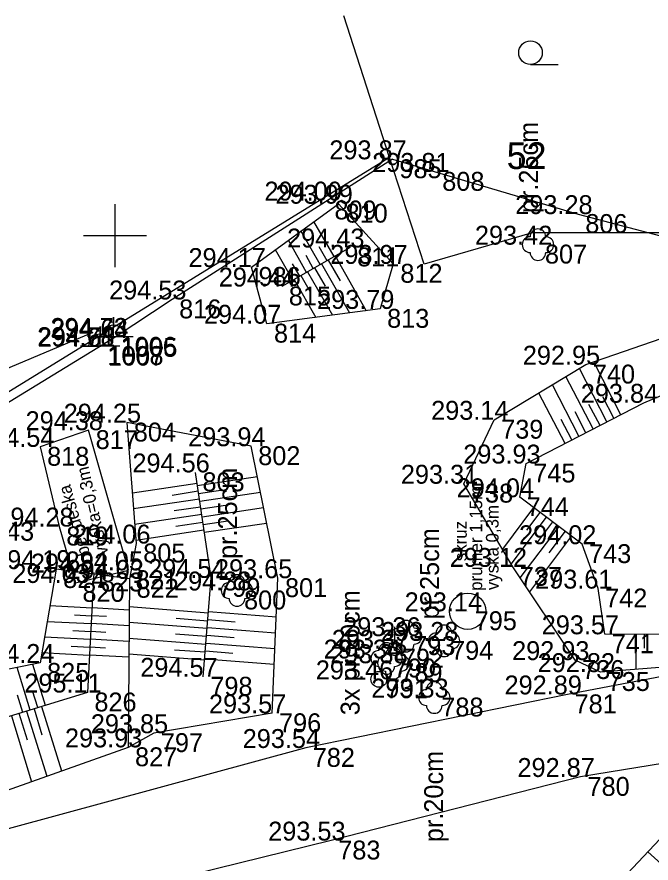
# Model space of a CAD drawing. Extents: x -599970 to -599524, y -1154772 to -1154457.
# Drawn here: x -599753.11 to -599732.99, y -1154619.91 to -1154593.05 of the extents above; entities that cross this region are included whole.
import ezdxf

# ---------------------------------------------------------------- set-up
doc = ezdxf.new("R2010")
doc.units = 0
for name, color, linetype in [('Z-KANALIZACNI SACHTY VPUSTI', 7, 'Continuous'), ('Z-KATASTRALNI MAPA', 7, 'Continuous'), ('Z-KRIZKY CTVERCOVE SITE', 7, 'Continuous'), ('Z-OCHRANNA TYC VODOVODU', 7, 'Continuous'), ('Z-PLOT DRATENY', 7, 'Continuous'), ('Z-PODROBNE BODY', 7, 'Continuous'), ('Z-PODROBNE BODY-CISLO', 7, 'Continuous'), ('Z-PODROBNE BODY-VYSKA', 7, 'Continuous'), ('Z-POPISY OBJEKTU A ZPEVNENYCH PLOCH', 7, 'Continuous'), ('Z-PRUMERY KMENU STROMU', 7, 'Continuous'), ('Z-SCHODY', 7, 'Continuous'), ('Z-SRAFOVANI SVAHU', 7, 'Continuous'), ('Z-STROMY ZNACKY KULTUR', 7, 'Continuous'), ('Z-TERENNI HRANY PATY', 7, 'Continuous'), ('Z-VYSKOVE BODY', 7, 'Continuous'), ('Z-ZPEVNENE PLOCHY', 7, 'Continuous')]:
    doc.layers.add(name, color=color, linetype=linetype)

msp = doc.modelspace()

# ---------------------------------------------------------------- linework, layer by layer
at = {"layer": 'Z-KANALIZACNI SACHTY VPUSTI'}
msp.add_circle((-599741.63, -1154614.08), 0.25, dxfattribs=at)
at = {"layer": 'Z-KATASTRALNI MAPA'}
for p, q in [((-599741.29, -1154597.51), (-599742.74, -1154593.02)), ((-599736.816, -1154594.56), (-599735.941, -1154594.56)), ((-599741.29, -1154597.51), (-599768.28, -1154614.14))]:
    msp.add_line(p, q, dxfattribs=at)
msp.add_lwpolyline([(-599730.43, -1154599.91), (-599736.76, -1154599.9), (-599740.19, -1154600.9), (-599741.29, -1154597.51)], dxfattribs=at)
msp.add_circle((-599736.816, -1154594.185), 0.375, dxfattribs=at)
at = {"layer": 'Z-KRIZKY CTVERCOVE SITE'}
for p, q in [((-599750, -1154601), (-599750, -1154599)), ((-599749, -1154600), (-599751, -1154600))]:
    msp.add_line(p, q, dxfattribs=at)
at = {"layer": 'Z-OCHRANNA TYC VODOVODU'}
msp.add_line((-599741.12, -1154612.885), (-599741.12, -1154612.414), dxfattribs=at)
msp.add_circle((-599741.12, -1154613.11), 0.225, dxfattribs=at)
at = {"layer": 'Z-PLOT DRATENY'}
for points in [[(-599741.2, -1154597.57), (-599748.19, -1154602.02), (-599750.03, -1154603.24), (-599757.54, -1154607.83), (-599759.8, -1154609.21), (-599765.35, -1154612.62), (-599767.84, -1154614.15), (-599771.68, -1154615.78), (-599777.02, -1154618.08), (-599780.14, -1154619.26), (-599783.61, -1154619.05), (-599791.83, -1154621.49)], [(-599741.2, -1154597.57), (-599735.3, -1154599.31), (-599728.67, -1154601.06), (-599725.81, -1154601.09), (-599719.24, -1154600.72), (-599713.57, -1154600.28), (-599704.41, -1154598.89), (-599697.5, -1154597.88)]]:
    msp.add_lwpolyline(points, dxfattribs=at)
at = {"layer": 'Z-PODROBNE BODY'}
for p, q in [((-599741.2, -1154597.57), (-599741.2, -1154597.57)), ((-599739.84, -1154597.97), (-599739.84, -1154597.97)), ((-599743.26, -1154598.88), (-599743.26, -1154598.88)), ((-599742.91, -1154598.98), (-599742.91, -1154598.98)), ((-599735.3, -1154599.31), (-599735.3, -1154599.31)), ((-599736.58, -1154600.28), (-599736.58, -1154600.28)), ((-599742.54, -1154600.37), (-599742.54, -1154600.37)), ((-599745.67, -1154600.99), (-599745.67, -1154600.99)), ((-599741.17, -1154600.89), (-599741.17, -1154600.89)), ((-599744.71, -1154601.61), (-599744.71, -1154601.61)), ((-599748.19, -1154602.02), (-599748.19, -1154602.02)), ((-599741.59, -1154602.32), (-599741.59, -1154602.32)), ((-599745.18, -1154602.79), (-599745.18, -1154602.79)), ((-599750.05, -1154603.21), (-599750.05, -1154603.21)), ((-599750.03, -1154603.24), (-599750.03, -1154603.24)), ((-599750.47, -1154603.5), (-599750.47, -1154603.5)), ((-599750.45, -1154603.52), (-599750.45, -1154603.52)), ((-599735.06, -1154604.09), (-599735.06, -1154604.09)), ((-599733.22, -1154605.3), (-599733.22, -1154605.3)), ((-599749.63, -1154605.93), (-599749.63, -1154605.93)), ((-599737.97, -1154605.84), (-599737.97, -1154605.84)), ((-599750.84, -1154606.17), (-599750.84, -1154606.17)), ((-599752.38, -1154606.7), (-599752.38, -1154606.7)), ((-599745.68, -1154606.68), (-599745.68, -1154606.68)), ((-599736.95, -1154607.23), (-599736.95, -1154607.23)), ((-599747.45, -1154607.51), (-599747.45, -1154607.51)), ((-599738.93, -1154607.87), (-599738.93, -1154607.87)), ((-599737.16, -1154608.3), (-599737.16, -1154608.3)), ((-599751.77, -1154609.23), (-599751.77, -1154609.23)), ((-599749.33, -1154609.77), (-599749.33, -1154609.77)), ((-599735.18, -1154609.79), (-599735.18, -1154609.79)), ((-599737.38, -1154610.51), (-599737.38, -1154610.51)), ((-599751.87, -1154610.58), (-599751.87, -1154610.58)), ((-599750.67, -1154610.69), (-599750.67, -1154610.69)), ((-599749.57, -1154610.62), (-599749.57, -1154610.62)), ((-599751.26, -1154611.02), (-599751.26, -1154611.02)), ((-599749.54, -1154610.89), (-599749.54, -1154610.89)), ((-599746.95, -1154610.86), (-599746.95, -1154610.86)), ((-599744.83, -1154610.87), (-599744.83, -1154610.87)), ((-599746.13, -1154611.26), (-599746.13, -1154611.26)), ((-599734.67, -1154611.2), (-599734.67, -1154611.2)), ((-599738.81, -1154611.92), (-599738.81, -1154611.92)), ((-599734.46, -1154612.65), (-599734.46, -1154612.65)), ((-599740.76, -1154612.71), (-599740.76, -1154612.71)), ((-599739.56, -1154612.86), (-599739.56, -1154612.86)), ((-599741.12, -1154613.11), (-599741.12, -1154613.11)), ((-599741.38, -1154613.42), (-599741.38, -1154613.42)), ((-599752.38, -1154613.56), (-599752.38, -1154613.56)), ((-599741.17, -1154613.57), (-599741.17, -1154613.57)), ((-599735.4, -1154613.47), (-599735.4, -1154613.47)), ((-599747.2, -1154614), (-599747.2, -1154614)), ((-599734.59, -1154613.85), (-599734.59, -1154613.85)), ((-599741.63, -1154614.08), (-599741.63, -1154614.08)), ((-599750.88, -1154614.5), (-599750.88, -1154614.5)), ((-599739.87, -1154614.66), (-599739.87, -1154614.66)), ((-599735.64, -1154614.56), (-599735.64, -1154614.56)), ((-599745.02, -1154615.16), (-599745.02, -1154615.16)), ((-599748.77, -1154615.79), (-599748.77, -1154615.79)), ((-599749.59, -1154616.24), (-599749.59, -1154616.24)), ((-599743.95, -1154616.26), (-599743.95, -1154616.26)), ((-599735.23, -1154617.18), (-599735.23, -1154617.18)), ((-599743.14, -1154619.2), (-599743.14, -1154619.2))]:
    msp.add_line(p, q, dxfattribs=at)
at = {"layer": 'Z-SCHODY'}
msp.add_circle((-599738.81, -1154611.92), 0.575, dxfattribs=at)
at = {"layer": 'Z-SRAFOVANI SVAHU'}
for points in [[(-599743.05, -1154600.66), (-599743.69, -1154599.55)], [(-599743.49, -1154600.91), (-599744.1, -1154599.84)], [(-599743.92, -1154601.16), (-599744.5, -1154600.14)], [(-599744.36, -1154601.41), (-599744.91, -1154600.44)], [(-599743.27, -1154600.79), (-599743.52, -1154600.35)], [(-599743.71, -1154601.04), (-599743.94, -1154600.62)], [(-599743.24, -1154600.77), (-599742.86, -1154601.43)], [(-599743.02, -1154600.64), (-599742.03, -1154602.38)], [(-599744.14, -1154601.28), (-599744.37, -1154600.89)], [(-599743.67, -1154601.02), (-599743.33, -1154601.6)], [(-599743.45, -1154600.89), (-599742.56, -1154602.45)], [(-599744.1, -1154601.26), (-599743.81, -1154601.78)], [(-599743.89, -1154601.14), (-599743.1, -1154602.52)], [(-599744.32, -1154601.39), (-599743.63, -1154602.59)], [(-599733.95, -1154605.68), (-599734.81, -1154604)], [(-599734.39, -1154605.91), (-599735.26, -1154604.21)], [(-599734.83, -1154606.13), (-599735.69, -1154604.47)], [(-599735.28, -1154606.36), (-599736.12, -1154604.73)], [(-599735.72, -1154606.59), (-599736.55, -1154604.99)], [(-599734.17, -1154605.79), (-599734.52, -1154605.11)], [(-599734.61, -1154606.02), (-599734.96, -1154605.35)], [(-599735.06, -1154606.25), (-599735.4, -1154605.59)], [(-599735.5, -1154606.48), (-599735.84, -1154605.83)], [(-599747.39, -1154607.93), (-599745.48, -1154607.64)], [(-599747.4, -1154607.86), (-599749.45, -1154608.17)], [(-599747.35, -1154608.18), (-599746.58, -1154608.06)], [(-599747.32, -1154608.36), (-599749.42, -1154608.67)], [(-599747.36, -1154608.11), (-599748.19, -1154608.24)], [(-599747.31, -1154608.42), (-599745.38, -1154608.14)], [(-599747.29, -1154608.61), (-599748.13, -1154608.73)], [(-599747.28, -1154608.67), (-599746.5, -1154608.55)], [(-599747.24, -1154608.92), (-599745.29, -1154608.63)], [(-599736.72, -1154608.63), (-599737.71, -1154609.95)], [(-599747.25, -1154608.85), (-599749.38, -1154609.17)], [(-599736.52, -1154608.78), (-599736.94, -1154609.34)], [(-599747.21, -1154609.1), (-599748.07, -1154609.23)], [(-599747.2, -1154609.16), (-599746.42, -1154609.05)], [(-599747.17, -1154609.41), (-599745.19, -1154609.12)], [(-599736.32, -1154608.93), (-599737.44, -1154610.42)], [(-599736.12, -1154609.08), (-599736.59, -1154609.71)], [(-599747.18, -1154609.35), (-599749.34, -1154609.67)], [(-599735.92, -1154609.23), (-599737.15, -1154610.86)], [(-599735.72, -1154609.38), (-599736.23, -1154610.06)], [(-599735.52, -1154609.53), (-599736.85, -1154611.3)], [(-599750.73, -1154611.82), (-599752.07, -1154611.75)], [(-599750.73, -1154611.8), (-599749.55, -1154611.87)], [(-599747.04, -1154611.98), (-599749.55, -1154611.78)], [(-599750.75, -1154612.07), (-599751.29, -1154612.04)], [(-599750.75, -1154612.05), (-599750.27, -1154612.08)], [(-599747.04, -1154611.93), (-599744.88, -1154612.1)], [(-599750.76, -1154612.32), (-599752.16, -1154612.25)], [(-599750.76, -1154612.3), (-599749.55, -1154612.37)], [(-599747.08, -1154612.47), (-599749.55, -1154612.28)], [(-599747.06, -1154612.23), (-599748.06, -1154612.15)], [(-599747.06, -1154612.18), (-599746.19, -1154612.25)], [(-599750.77, -1154612.57), (-599751.34, -1154612.54)], [(-599750.77, -1154612.55), (-599750.29, -1154612.58)], [(-599747.1, -1154612.72), (-599748.08, -1154612.65)], [(-599747.07, -1154612.43), (-599744.91, -1154612.6)], [(-599750.79, -1154612.82), (-599752.24, -1154612.74)], [(-599750.79, -1154612.8), (-599749.56, -1154612.87)], [(-599747.12, -1154612.97), (-599749.56, -1154612.78)], [(-599747.09, -1154612.68), (-599746.22, -1154612.75)], [(-599733.46, -1154612.66), (-599733.47, -1154613.76)], [(-599733.21, -1154612.66), (-599733.21, -1154613.09)], [(-599750.8, -1154613.07), (-599751.39, -1154613.04)], [(-599750.8, -1154613.05), (-599750.3, -1154613.08)], [(-599747.14, -1154613.22), (-599748.11, -1154613.15)], [(-599747.13, -1154613.18), (-599746.26, -1154613.25)], [(-599747.11, -1154612.93), (-599744.93, -1154613.1)], [(-599750.82, -1154613.32), (-599752.32, -1154613.24)], [(-599750.81, -1154613.3), (-599749.56, -1154613.37)], [(-599747.16, -1154613.47), (-599749.56, -1154613.28)], [(-599747.15, -1154613.43), (-599744.95, -1154613.6)], [(-599752.69, -1154615.06), (-599753.11, -1154613.71)], [(-599752.21, -1154614.91), (-599752.61, -1154613.61)], [(-599752.45, -1154614.98), (-599752.62, -1154614.45)], [(-599752.93, -1154615.13), (-599753.1, -1154614.58)], [(-599752.57, -1154615.02), (-599752.32, -1154615.84)], [(-599752.33, -1154614.94), (-599751.7, -1154616.99)], [(-599753.29, -1154615.24), (-599752.65, -1154617.33)], [(-599753.05, -1154615.16), (-599752.79, -1154616)], [(-599752.81, -1154615.09), (-599752.17, -1154617.16)], [(-599731.61, -1154620.89), (-599733.09, -1154619.56)]]:
    msp.add_lwpolyline(points, dxfattribs=at)
at = {"layer": 'Z-STROMY ZNACKY KULTUR'}
for centre in [(-599736.58, -1154600.28), (-599746.13, -1154611.26), (-599740.76, -1154612.71), (-599739.56, -1154612.86), (-599741.38, -1154613.42), (-599741.17, -1154613.57), (-599739.87, -1154614.66)]:
    msp.add_circle(centre, 0.00025, dxfattribs=at)
for centre, start, end in [((-599736.83, -1154600.28), 90, 270), ((-599736.58, -1154600.03), 0, 180), ((-599736.33, -1154600.28), 270, 90), ((-599736.58, -1154600.53), 180, 360), ((-599746.13, -1154611.01), 0, 180), ((-599746.38, -1154611.26), 90, 270), ((-599745.88, -1154611.26), 270, 90), ((-599746.13, -1154611.51), 180, 360), ((-599740.76, -1154612.46), 0, 180), ((-599739.56, -1154612.61), 0, 180), ((-599741.01, -1154612.71), 90, 270), ((-599740.51, -1154612.71), 270, 90), ((-599739.81, -1154612.86), 90, 270), ((-599739.31, -1154612.86), 270, 90), ((-599741.38, -1154613.17), 0, 180), ((-599741.63, -1154613.42), 90, 270), ((-599741.17, -1154613.32), 0, 180), ((-599741.13, -1154613.42), 270, 90), ((-599740.76, -1154612.96), 180, 360), ((-599739.56, -1154613.11), 180, 360), ((-599741.42, -1154613.57), 90, 270), ((-599740.92, -1154613.57), 270, 90), ((-599741.38, -1154613.67), 180, 360), ((-599741.17, -1154613.82), 180, 360), ((-599739.87, -1154614.41), 0, 180), ((-599740.12, -1154614.66), 90, 270), ((-599739.62, -1154614.66), 270, 90), ((-599739.87, -1154614.91), 180, 360)]:
    msp.add_arc(centre, 0.25, start, end, dxfattribs=at)
at = {"layer": 'Z-TERENNI HRANY PATY'}
for points in [[(-599745.18, -1154602.79), (-599745.67, -1154600.99), (-599742.91, -1154598.98), (-599741.17, -1154600.89), (-599741.59, -1154602.32)], [(-599729.05, -1154602.01), (-599721.76, -1154601.98), (-599713.7, -1154601.68), (-599707.23, -1154600.75), (-599702.22, -1154599.95), (-599702.11, -1154604.78), (-599703.83, -1154606.55), (-599707.44, -1154607.94), (-599715.66, -1154610.06), (-599723.72, -1154611.89), (-599730.02, -1154613.49), (-599734.59, -1154613.85), (-599735.4, -1154613.47), (-599737.38, -1154610.51), (-599738.93, -1154607.87), (-599737.97, -1154605.84), (-599735.06, -1154604.09), (-599729.05, -1154602.01)], [(-599742.54, -1154600.37), (-599744.71, -1154601.61)], [(-599706.69, -1154601.61), (-599704.55, -1154601.39), (-599703.42, -1154603.18), (-599703.99, -1154604.61), (-599707.71, -1154606.89), (-599711.67, -1154607.23), (-599718.57, -1154608.46), (-599724.85, -1154610.8), (-599730.76, -1154612.67), (-599734.46, -1154612.65)], [(-599741.59, -1154602.32), (-599745.18, -1154602.79)], [(-599734.46, -1154612.65), (-599734.67, -1154611.2), (-599735.18, -1154609.79), (-599737.16, -1154608.3), (-599736.95, -1154607.23), (-599733.22, -1154605.3), (-599730.19, -1154604.02), (-599725.57, -1154603.88), (-599719.1, -1154602.65), (-599713.56, -1154602.84), (-599710.91, -1154602.51)], [(-599749.63, -1154605.93), (-599749.33, -1154609.77), (-599749.54, -1154610.89)], [(-599745.02, -1154615.16), (-599744.83, -1154610.87), (-599745.68, -1154606.68), (-599749.63, -1154605.93)], [(-599747.2, -1154614), (-599746.95, -1154610.86), (-599747.45, -1154607.51)], [(-599749.54, -1154610.89), (-599751.87, -1154610.58), (-599752.38, -1154613.56), (-599757.6, -1154614.61), (-599759.09, -1154612.31), (-599761.33, -1154613.69)], [(-599750.67, -1154610.69), (-599750.88, -1154614.5), (-599755.48, -1154615.91), (-599758.65, -1154615.71), (-599760.14, -1154613.54)], [(-599749.54, -1154610.89), (-599749.59, -1154616.24), (-599757.01, -1154618.88), (-599758.7, -1154617.18), (-599760.39, -1154616), (-599761.33, -1154613.69)], [(-599706.85, -1154650.78), (-599713.18, -1154651.03), (-599721.07, -1154652.91), (-599723.76, -1154645.8), (-599725.1, -1154640.23), (-599727.83, -1154634.18), (-599728.54, -1154633), (-599732.31, -1154631.05), (-599735.11, -1154628.08), (-599735.76, -1154623.86), (-599735.73, -1154623.89), (-599734.76, -1154621.33), (-599730.32, -1154616.62), (-599722.93, -1154615.52), (-599713.66, -1154613.52), (-599712.4, -1154614.76), (-599710.05, -1154618.59), (-599710.54, -1154622.05), (-599712.9, -1154623.66), (-599717.25, -1154628.18), (-599716.96, -1154629.04), (-599714.58, -1154631.6), (-599714.4, -1154633.54), (-599711.28, -1154633.06)], [(-599745.02, -1154615.16), (-599748.77, -1154615.79), (-599749.59, -1154616.24)]]:
    msp.add_lwpolyline(points, dxfattribs=at)
at = {"layer": 'Z-VYSKOVE BODY'}
for p, q in [((-599750.05, -1154602.585), (-599750.05, -1154602.835)), ((-599750.05, -1154602.835), (-599750.05, -1154602.585)), ((-599750.05, -1154603.21), (-599750.05, -1154602.585)), ((-599750.05, -1154602.585), (-599750.05, -1154602.835)), ((-599750.47, -1154602.875), (-599750.47, -1154603.125)), ((-599750.47, -1154603.125), (-599750.47, -1154602.875)), ((-599750.47, -1154603.5), (-599750.47, -1154602.875)), ((-599750.47, -1154602.875), (-599750.47, -1154603.125)), ((-599764.3, -1154608.79), (-599750.7, -1154603.06)), ((-599749.425, -1154603.21), (-599750.675, -1154603.21)), ((-599750.675, -1154603.21), (-599750.05, -1154603.21)), ((-599749.425, -1154603.21), (-599750.05, -1154603.21)), ((-599749.845, -1154603.5), (-599751.095, -1154603.5)), ((-599751.095, -1154603.5), (-599750.47, -1154603.5)), ((-599749.845, -1154603.5), (-599750.47, -1154603.5))]:
    msp.add_line(p, q, dxfattribs=at)
for centre, start, end in [((-599750.05, -1154603.21), 90, 180), ((-599750.05, -1154603.21), 0, 90), ((-599750.47, -1154603.5), 90, 180), ((-599750.47, -1154603.5), 0, 90)]:
    msp.add_arc(centre, 0.375, start, end, dxfattribs=at)
at = {"layer": 'Z-ZPEVNENE PLOCHY'}
for points in [[(-599750.84, -1154606.17), (-599752.38, -1154606.7), (-599751.77, -1154609.23), (-599751.26, -1154611.02), (-599749.57, -1154610.62), (-599750.84, -1154606.17)], [(-599671.02, -1154617.03), (-599671.63, -1154613.35), (-599675.05, -1154613.45), (-599680.32, -1154612.41), (-599686.62, -1154610.91), (-599694.45, -1154609.33), (-599700.34, -1154608.57), (-599705.79, -1154608.71), (-599715.78, -1154610.69), (-599725.58, -1154612.61), (-599730.02, -1154613.49), (-599735.64, -1154614.56), (-599743.95, -1154616.26), (-599754.96, -1154619.25), (-599762.63, -1154622.27), (-599761.65, -1154625.43)], [(-599671.02, -1154617.03), (-599674, -1154617.11), (-599674.74, -1154618.09), (-599672.97, -1154619.61), (-599672.99, -1154619.63), (-599673.43, -1154624.97), (-599672.1, -1154632.73), (-599679.37, -1154632.4), (-599679.21, -1154625.35), (-599679.14, -1154619.7), (-599679.61, -1154616.32), (-599687.06, -1154613.66), (-599695, -1154612.23), (-599700.47, -1154611.47), (-599705.51, -1154611.86), (-599715.16, -1154613.61), (-599724.96, -1154615.5), (-599735.23, -1154617.18), (-599743.14, -1154619.2), (-599754.14, -1154621.91)]]:
    msp.add_lwpolyline(points, dxfattribs=at)

# ---------------------------------------------------------------- texts
at = {"layer": 'Z-KATASTRALNI MAPA'}
msp.add_text('52', height=0.85, dxfattribs=at).set_placement((-599737.573, -1154597.88))
at = {"layer": 'Z-PODROBNE BODY-CISLO'}
for s, p in [(' 985', (-599741.2, -1154598.17)), (' 808', (-599739.84, -1154598.57)), (' 809', (-599743.26, -1154599.48)), (' 810', (-599742.91, -1154599.58)), (' 806', (-599735.3, -1154599.91)), (' 807', (-599736.58, -1154600.88)), (' 811', (-599742.54, -1154600.97)), (' 986', (-599745.67, -1154601.59)), (' 812', (-599741.17, -1154601.49)), (' 815', (-599744.71, -1154602.21)), (' 816', (-599748.19, -1154602.62)), (' 813', (-599741.59, -1154602.92)), (' 814', (-599745.18, -1154603.39)), (' 1006', (-599750.05, -1154603.81)), (' 1005', (-599750.03, -1154603.84)), (' 1008', (-599750.47, -1154604.1)), (' 1007', (-599750.45, -1154604.12)), (' 740', (-599735.06, -1154604.69)), (' 804', (-599749.63, -1154606.53)), (' 739', (-599737.97, -1154606.44)), (' 817', (-599750.84, -1154606.77)), (' 818', (-599752.38, -1154607.3)), (' 802', (-599745.68, -1154607.28)), (' 745', (-599736.95, -1154607.83)), (' 803', (-599747.45, -1154608.11)), (' 738', (-599738.93, -1154608.47)), (' 744', (-599737.16, -1154608.9)), (' 843', (-599754.13, -1154609.68)), (' 819', (-599751.77, -1154609.83)), (' 805', (-599749.33, -1154610.37)), (' 743', (-599735.18, -1154610.39)), (' 737', (-599737.38, -1154611.11)), (' 824', (-599751.87, -1154611.18)), (' 823', (-599750.67, -1154611.29)), (' 821', (-599749.57, -1154611.22)), (' 820', (-599751.26, -1154611.62)), (' 822', (-599749.54, -1154611.49)), (' 799', (-599746.95, -1154611.46)), (' 801', (-599744.83, -1154611.47)), (' 800', (-599746.13, -1154611.86)), (' 742', (-599734.67, -1154611.8)), (' 795', (-599738.81, -1154612.52)), (' 741', (-599734.46, -1154613.25)), (' 793', (-599740.76, -1154613.31)), (' 794', (-599739.56, -1154613.46)), (' 792', (-599741.12, -1154613.71)), (' 790', (-599741.38, -1154614.02)), (' 736', (-599735.4, -1154614.07)), (' 825', (-599752.38, -1154614.16)), (' 789', (-599741.17, -1154614.17)), (' 798', (-599747.2, -1154614.6)), (' 735', (-599734.59, -1154614.45)), (' 791', (-599741.63, -1154614.68)), (' 826', (-599750.88, -1154615.1)), (' 788', (-599739.87, -1154615.26)), (' 781', (-599735.64, -1154615.16)), (' 796', (-599745.02, -1154615.76)), (' 797', (-599748.77, -1154616.39)), (' 827', (-599749.59, -1154616.84)), (' 782', (-599743.95, -1154616.86)), (' 780', (-599735.23, -1154617.78)), (' 783', (-599743.14, -1154619.8))]:
    msp.add_text(s, height=0.6, dxfattribs=at).set_placement(p)
at = {"layer": 'Z-PODROBNE BODY-VYSKA'}
for s, p in [('293.87 ', (-599743.2, -1154597.57)), ('293.81 ', (-599741.84, -1154597.97)), ('294.00 ', (-599745.26, -1154598.88)), ('293.99 ', (-599744.91, -1154598.98)), ('293.28 ', (-599737.3, -1154599.31)), ('294.43 ', (-599744.54, -1154600.37)), ('293.42 ', (-599738.58, -1154600.28)), ('293.97 ', (-599743.17, -1154600.89)), ('294.17 ', (-599747.67, -1154600.99)), ('294.44 ', (-599746.71, -1154601.61)), ('294.53 ', (-599750.19, -1154602.02)), ('293.79 ', (-599743.59, -1154602.32)), ('294.07 ', (-599747.18, -1154602.79)), ('294.73 ', (-599752.05, -1154603.21)), ('294.64 ', (-599752.03, -1154603.24)), ('294.78 ', (-599752.47, -1154603.5)), ('294.61 ', (-599752.45, -1154603.52)), ('292.95 ', (-599737.06, -1154604.09)), ('293.84 ', (-599735.22, -1154605.3)), ('294.25 ', (-599751.63, -1154605.93)), ('293.14 ', (-599739.97, -1154605.84)), ('294.38 ', (-599752.84, -1154606.17)), ('294.54 ', (-599754.38, -1154606.7)), ('293.94 ', (-599747.68, -1154606.68)), ('293.93 ', (-599738.95, -1154607.23)), ('294.56 ', (-599749.45, -1154607.51)), ('293.31 ', (-599740.93, -1154607.87)), ('294.04 ', (-599739.16, -1154608.3)), ('294.28 ', (-599753.77, -1154609.23)), ('294.06 ', (-599751.33, -1154609.77)), ('294.02 ', (-599737.18, -1154609.79)), ('294.19 ', (-599753.87, -1154610.58)), ('293.12 ', (-599739.38, -1154610.51)), ('294.82 ', (-599752.67, -1154610.69)), ('294.05 ', (-599751.57, -1154610.62)), ('294.03 ', (-599753.26, -1154611.02)), ('294.03 ', (-599751.54, -1154610.89)), ('294.54 ', (-599748.95, -1154610.86)), ('293.65 ', (-599746.83, -1154610.87)), ('294.38 ', (-599748.13, -1154611.26)), ('293.61 ', (-599736.67, -1154611.2)), ('293.14 ', (-599740.81, -1154611.92)), ('293.36 ', (-599742.76, -1154612.71)), ('293.57 ', (-599736.46, -1154612.65)), ('293.28 ', (-599741.56, -1154612.86)), ('293.37 ', (-599743.12, -1154613.11)), ('293.34 ', (-599743.38, -1154613.42)), ('292.93 ', (-599737.4, -1154613.47)), ('294.24 ', (-599754.38, -1154613.56)), ('293.38 ', (-599743.17, -1154613.57)), ('294.57 ', (-599749.2, -1154614)), ('292.82 ', (-599736.59, -1154613.85)), ('293.46 ', (-599743.63, -1154614.08)), ('295.11 ', (-599752.88, -1154614.5)), ('292.89 ', (-599737.64, -1154614.56)), ('293.33 ', (-599741.87, -1154614.66)), ('293.57 ', (-599747.02, -1154615.16)), ('293.85 ', (-599750.77, -1154615.79)), ('293.93 ', (-599751.59, -1154616.24)), ('293.54 ', (-599745.95, -1154616.26)), ('292.87 ', (-599737.23, -1154617.18)), ('293.53 ', (-599745.14, -1154619.2))]:
    msp.add_text(s, height=0.6, dxfattribs=at).set_placement(p)
at = {"layer": 'Z-POPISY OBJEKTU A ZPEVNENYCH PLOCH'}
for s, p in [('prumer 1,15m', (-599738.35, -1154611.27)), ('vyska 0,3m', (-599737.83, -1154611.25))]:
    msp.add_text(s, height=0.4, rotation=90, dxfattribs=at).set_placement(p)
at = {"layer": 'Z-PRUMERY KMENU STROMU'}
for s, p in [('pr.25cm', (-599736.58, -1154599.28)), ('pr.25cm', (-599746.13, -1154610.26)), ('pr.25cm', (-599739.72, -1154612.18)), ('3x pr.20cm', (-599742.24, -1154615.22)), ('pr.20cm', (-599739.59, -1154619.25))]:
    msp.add_text(s, height=0.6, rotation=90, dxfattribs=at).set_placement(p)
at = {"layer": 'Z-SCHODY'}
for s, rotation, p in [('vyska=0,3m', 102.875, (-599750.21, -1154610.09)), ('bet.deska', 105.9284, (-599750.79, -1154610.1)), ('skruz', 90, (-599738.84, -1154610.33))]:
    msp.add_text(s, height=0.4, rotation=rotation, dxfattribs=at).set_placement(p)

doc.saveas('drawing.dxf')
